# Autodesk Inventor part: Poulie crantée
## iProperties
Author: Philippe
Shininess: 20.0
Angle Display Precision: 2
Document Length Units: 11269
Document Angle Units: 11283
Document Time Units: 11279
Document Mass Units: 11290
Document Length Units Precision: 3
Document Angle Units Precision: 2
Compacted: False
PropertySet Name: _Private Model Information
Created: 2002-06
Part Number: Poulie crantée
Material: A-S13
Document SubType Name: Modélisation
Designer: Philippe
Control State: 0
Master: False
Checked Out: False
PropertySet Name: Design Tracking Control
Density: 2.71
Volumn: 5.713244111924164
Area: 35.1709087850959
PropertySet Name: Model Information
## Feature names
1. Révolution1:Enveloppe [Revolution]
2. Extrusion1:Première dent creusée
3. Réseau circulaire1:Toutes les dents [Circular Pattern]
